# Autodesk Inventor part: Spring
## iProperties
Created: 2010-09
Part Number: Spring
Document SubType Name: Modeling
Designer: nguyenducthang
Density: 1 g/cm^3
Mass: 0.00136336 g
Surface Area: 0.138849 cm^2
Volume: 0.00136336 cm^3
Author: nguyenducthang
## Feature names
1. Sweep1
